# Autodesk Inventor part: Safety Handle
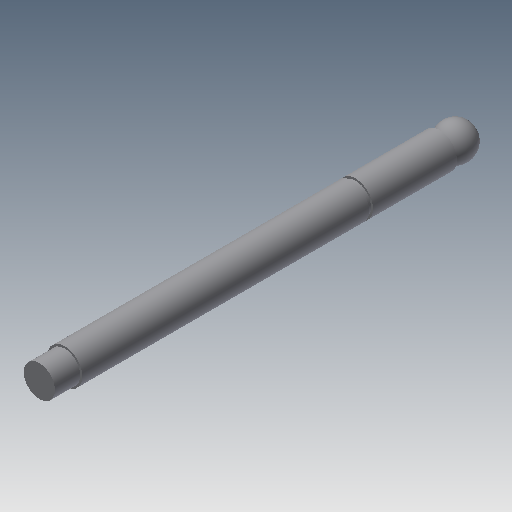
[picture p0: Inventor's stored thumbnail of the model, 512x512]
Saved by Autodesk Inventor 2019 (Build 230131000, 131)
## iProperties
Shininess: 77.0
Length Units: 11269
Angle Units: 11279
Time Units: 11290
Mass Units: 11283
Length Display Precision: 3
Angle Display Precision: 2
Created: 2002-02
Part Number: Safety Handle
Document SubType Name: Modeling
Designer: ***
Density: 1 g/cm^3
Material: Generic
Mass: 54.3914 g
Surface Area: 130.219 cm^2
Volume: 54.3914 cm^3
Appearance: Default
Density: 0.0
Volumn: 0.0
Area: 0.0
PropertySet Name: Model Information
Control State: 0
Master: False
Checked Out: False
Author: ***
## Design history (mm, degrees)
sketch "Sketch1"
  geometry: L1 (0, 205)-(8, 205); L2 (8, 205)-(8, 192); L3 (8, 192)-(9, 192); L4 (9, 192)-(9, 45); L5 (9, 45)-(8, 45); L6 (8, 45)-(8, 43); L7 (8, 43)-(9, 43); L8 (9, 43)-(9, 0); L9 (9, 0)-(0, 0); L10 (0, 0)-(0, 205)
  constraints: 20 end point, 7 parallel, 1 collinear, 1 horizontal, 1 perpendicular
  dimensions: "d0" = 13 distance of L1.end L2.end; "d1" = 2 distance of L4.end L7.end; "d2" = 43 distance of L7.end L8.end; "d3" = 205 distance of L9.end L1.start; "d4" = 16 diameter of L2 L10; "d5" = 18 diameter of L4 L10; "d6" = 16 diameter of L6.end L10
revolve "Revolution1" sketch "Sketch1" stored, may be unused: angle "d7" = 90 deg
sketch "Sketch2"
  geometry: L1 (0, 1)-(0, -17); L2 (-9, 0)-(9, 0) reference; A1 r 9 centre (0, -8) between (0, -17) and (0, 1)
  constraints: 2 end point, 2 point on circle, 1 centre point, 1 midpoint, 1 vertical
  dimensions: "d8" = 9 radius of A1; "d9" = 1 distance from line of L2 L1.start
revolve "Revolution2" sketch "Sketch2" stored, may be unused: angle "d10" = 90 deg
body "Solid1"
